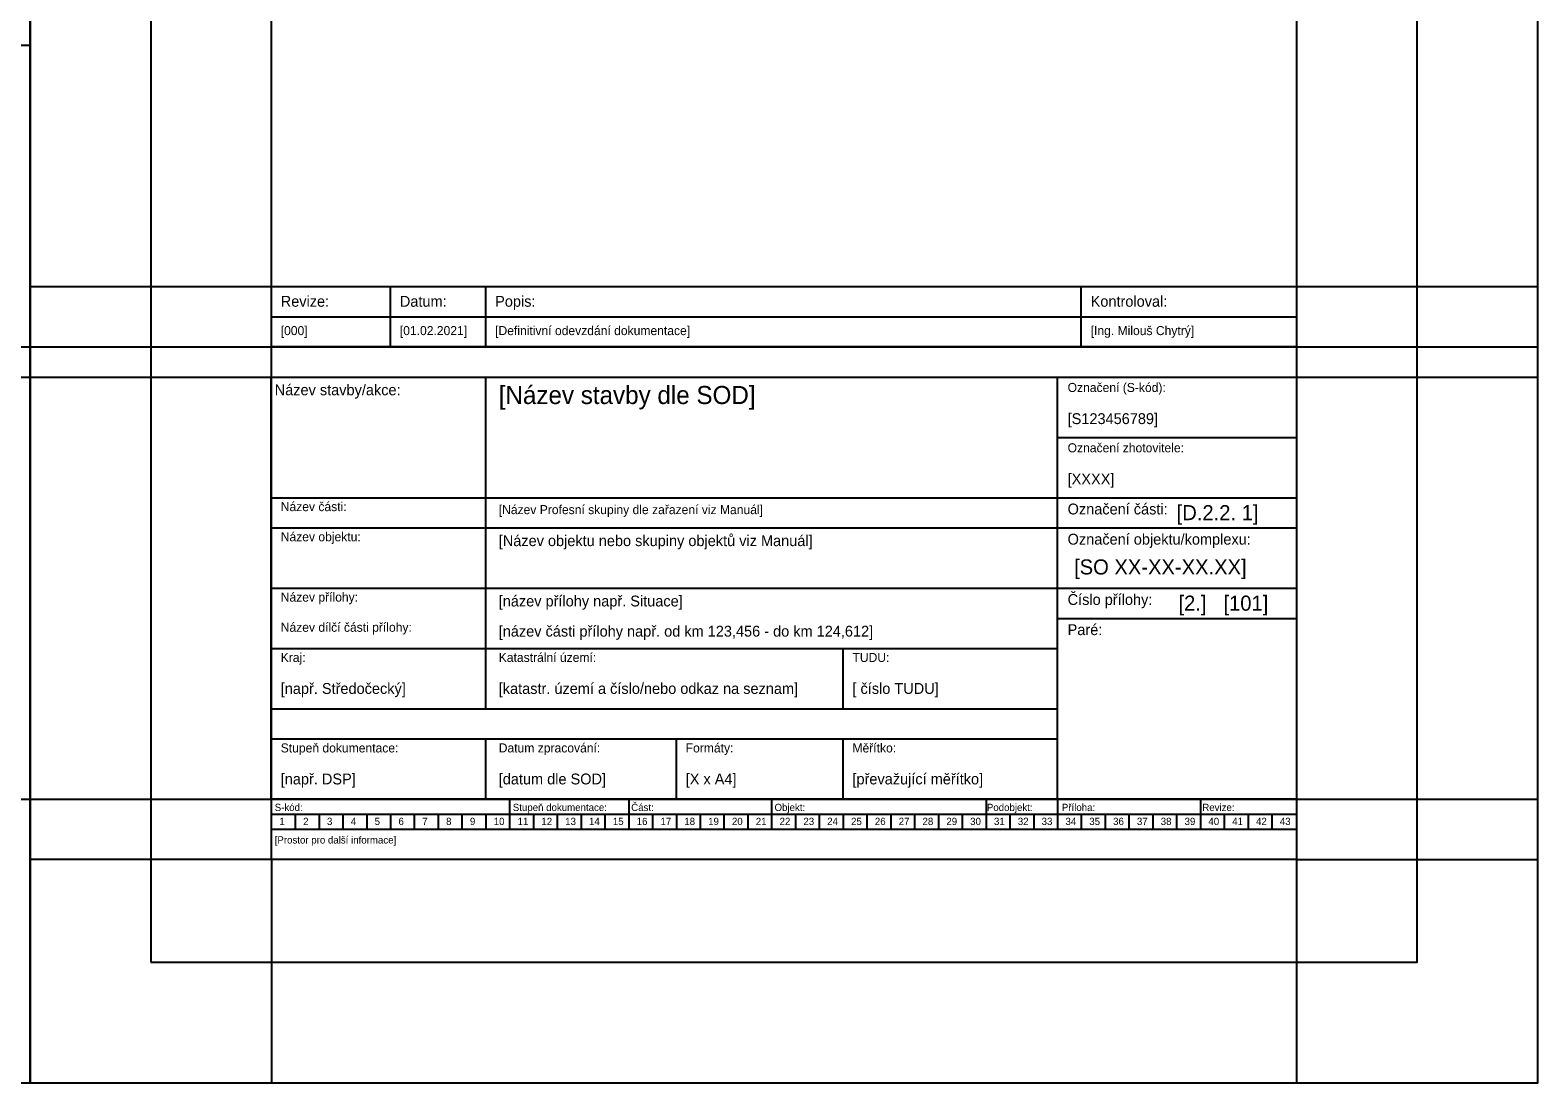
# Model space of a CAD drawing. Extents: x -27 to 48, y -2 to 33.
# Drawn here: x 23 to 48, y -2 to 15.45 of the extents above; entities that cross this region are included whole.
import ezdxf

# ---------------------------------------------------------------- set-up
doc = ezdxf.new("R2010")
doc.units = 0
for name, color, linetype in [('Default', 7, 'Continuous'), ('Rozpiska_pole_1', 7, 'Continuous'), ('Rozpiska_pole_4', 7, 'Continuous'), ('Rozpiska_pole_7', 7, 'Continuous'), ('Rozpiska_pole_8', 7, 'Continuous')]:
    doc.layers.add(name, color=color, linetype=linetype)

msp = doc.modelspace()

# ---------------------------------------------------------------- linework, layer by layer
at = {"layer": 'Default'}
for p, q in [((-2, 15.2), (23, 15.2)), ((23, 11.2), (48, 11.2)), ((-2, 10.2), (23, 10.2)), ((23, 10.2), (48, 10.2)), ((-2, 9.7), (23, 9.7)), ((23, 9.7), (48, 9.7)), ((-2, 2.7), (23, 2.7)), ((23, 2.7), (48, 2.7)), ((27, 1.7), (23, 1.7)), ((27, 1.7), (27, -2)), ((44, 1.7), (48, 1.7)), ((44, 1.7), (44, -2))]:
    msp.add_line(p, q, dxfattribs=at)
for points in [[(-2, -2), (23, -2), (23, 31.7), (-2, 31.7)], [(23, -2), (48, -2), (48, 31.7), (23, 31.7)], [(25, 0), (46, 0), (46, 29.7), (25, 29.7)]]:
    msp.add_lwpolyline(points, close=True, dxfattribs=at)
at = {"layer": 'Rozpiska_pole_1'}
msp.add_lwpolyline([(27, 27.7), (44, 27.7), (44, 1.7), (27, 1.7)], close=True, dxfattribs=at)
at = {"layer": 'Rozpiska_pole_4'}
for p, q in [((28.975, 10.2), (28.975, 11.2)), ((30.555, 10.2), (30.555, 11.2)), ((40.43, 10.2), (40.43, 11.2)), ((27, 10.7), (44, 10.7))]:
    msp.add_line(p, q, dxfattribs=at)
msp.add_lwpolyline([(27, 11.2), (44, 11.2), (44, 10.2), (27, 10.2)], close=True, dxfattribs=at)
at = {"layer": 'Rozpiska_pole_7'}
for p, q in [((30.555, 4.2), (30.555, 9.7)), ((40.035, 8.7), (44, 8.7)), ((27, 7.7), (40.035, 7.7)), ((40.035, 7.7), (44, 7.7)), ((27, 7.2), (40.035, 7.2)), ((40.035, 7.2), (44, 7.2)), ((27, 6.2), (40.035, 6.2)), ((40.035, 6.2), (44, 6.2)), ((40.035, 5.7), (44, 5.7)), ((27, 5.2), (40.035, 5.2)), ((36.48, 4.2), (36.48, 5.2)), ((27, 4.2), (40.035, 4.2)), ((27, 3.7), (40.035, 3.7)), ((30.555, 2.7), (30.555, 3.7)), ((33.715, 2.7), (33.715, 3.7)), ((36.48, 2.7), (36.48, 3.7))]:
    msp.add_line(p, q, dxfattribs=at)
for points in [[(26.999, 9.7), (43.999, 9.7), (43.999, 2.7), (26.999, 2.7)], [(44, 2.7), (40.035, 2.7), (40.035, 9.7), (44, 9.7)]]:
    msp.add_lwpolyline(points, close=True, dxfattribs=at)
at = {"layer": 'Rozpiska_pole_8'}
for p, q in [((30.95, 2.7), (30.95, 2.2)), ((32.925, 2.7), (32.925, 2.2)), ((35.295, 2.7), (35.295, 2.2)), ((38.85, 2.7), (38.85, 2.2)), ((40.035, 2.7), (40.035, 2.2)), ((42.405, 2.7), (42.405, 2.2)), ((44, 2.45), (27, 2.45)), ((27.395, 2.45), (27.395, 2.2)), ((27.79, 2.45), (27.79, 2.2)), ((28.185, 2.45), (28.185, 2.2)), ((28.58, 2.45), (28.58, 2.2)), ((28.975, 2.45), (28.975, 2.2)), ((29.37, 2.45), (29.37, 2.2)), ((29.765, 2.45), (29.765, 2.2)), ((30.16, 2.45), (30.16, 2.2)), ((30.555, 2.45), (30.555, 2.2)), ((31.345, 2.45), (31.345, 2.2)), ((31.74, 2.45), (31.74, 2.2)), ((32.135, 2.45), (32.135, 2.2)), ((32.53, 2.45), (32.53, 2.2)), ((33.32, 2.45), (33.32, 2.2)), ((33.715, 2.45), (33.715, 2.2)), ((34.11, 2.45), (34.11, 2.2)), ((34.505, 2.45), (34.505, 2.2)), ((34.9, 2.45), (34.9, 2.2)), ((35.69, 2.45), (35.69, 2.2)), ((36.085, 2.45), (36.085, 2.2)), ((36.48, 2.45), (36.48, 2.2)), ((36.875, 2.45), (36.875, 2.2)), ((37.27, 2.45), (37.27, 2.2)), ((37.665, 2.45), (37.665, 2.2)), ((38.06, 2.45), (38.06, 2.2)), ((38.455, 2.45), (38.455, 2.2)), ((39.245, 2.45), (39.245, 2.2)), ((39.64, 2.45), (39.64, 2.2)), ((40.43, 2.45), (40.43, 2.2)), ((40.825, 2.45), (40.825, 2.2)), ((41.22, 2.45), (41.22, 2.2)), ((41.615, 2.45), (41.615, 2.2)), ((42.01, 2.45), (42.01, 2.2)), ((42.8, 2.45), (42.8, 2.2)), ((43.195, 2.45), (43.195, 2.2)), ((43.59, 2.45), (43.59, 2.2))]:
    msp.add_line(p, q, dxfattribs=at)
msp.add_lwpolyline([(27, 2.7), (44, 2.7), (44, 2.2), (27, 2.2)], close=True, dxfattribs=at)

# ---------------------------------------------------------------- texts
at = {"layer": 'Rozpiska_pole_4'}
for s, height, p in [('Revize:', 0.18, (27.155, 10.865)), ('Datum:', 0.18, (29.13, 10.865)), ('Popis:', 0.18, (30.71, 10.865)), ('Kontroloval:', 0.18, (40.585, 10.865)), ('[000]', 0.15, (27.155, 10.395)), ('[01.02.2021]', 0.15, (29.13, 10.395)), ('[Definitivní odevzdání dokumentace]', 0.15, (30.71, 10.395)), ('[Ing. Milouš Chytrý]', 0.15, (40.585, 10.395))]:
    msp.add_text(s, height=height, dxfattribs=at).set_placement(p)
at = {"layer": 'Rozpiska_pole_7'}
for s, height, p in [('Název stavby/akce:', 0.18, (27.055, 9.397)), ('[Název stavby dle SOD]', 0.3, (30.77, 9.252)), ('Označení (S-kód):', 0.15, (40.203, 9.452)), ('[S123456789]', 0.18, (40.203, 8.92)), ('Označení zhotovitele:', 0.15, (40.203, 8.452)), ('[XXXX]', 0.18, (40.203, 7.92)), ('Název části:', 0.15, (27.155, 7.477)), ('[Název Profesní skupiny dle zařazení viz Manuál]', 0.15, (30.77, 7.427)), ('Označení části:', 0.18, (40.203, 7.422)), ('[D.2.2. 1]', 0.25, (42.011, 7.327)), ('Název objektu:', 0.15, (27.155, 6.977)), ('[Název objektu nebo skupiny objektů viz Manuál]', 0.18, (30.77, 6.897)), ('Označení objektu/komplexu:', 0.18, (40.203, 6.922)), ('[SO XX-XX-XX.XX]', 0.25, (40.31, 6.427)), ('Název přílohy:', 0.15, (27.155, 5.977)), ('[název přílohy např. Situace]', 0.18, (30.77, 5.897)), ('Číslo přílohy:', 0.18, (40.203, 5.922)), ('[2.]', 0.25, (42.041, 5.827)), ('[101]', 0.25, (42.787, 5.827)), ('Název dílčí části přílohy:', 0.15, (27.155, 5.477)), ('[název části přílohy např. od km 123,456 - do km 124,612]', 0.18, (30.77, 5.397)), ('Paré:', 0.18, (40.203, 5.422)), ('Kraj:', 0.15, (27.155, 4.977)), ('Katastrální území:', 0.15, (30.77, 4.977)), ('TUDU:', 0.15, (36.635, 4.977)), ('[např. Středočecký]', 0.18, (27.155, 4.447)), ('[katastr. území a číslo/nebo odkaz na seznam]', 0.18, (30.77, 4.447)), ('[ číslo TUDU]', 0.18, (36.635, 4.447)), ('Stupeň dokumentace:', 0.15, (27.155, 3.477)), ('Datum zpracování:', 0.15, (30.77, 3.477)), ('Formáty:', 0.15, (33.87, 3.477)), ('Měřítko:', 0.15, (36.635, 3.477)), ('[např. DSP]', 0.18, (27.155, 2.947)), ('[datum dle SOD]', 0.18, (30.77, 2.947)), ('[X x A4]', 0.18, (33.87, 2.947)), ('[převažující měřítko]', 0.18, (36.635, 2.947))]:
    msp.add_text(s, height=height, dxfattribs=at).set_placement(p)
at = {"layer": 'Rozpiska_pole_8'}
for s, p in [('S-kód:', (27.055, 2.506)), ('Stupeň dokumentace:', (31.003, 2.506)), ('Část:', (32.966, 2.506)), ('Objekt:', (35.343, 2.506)), ('Podobjekt:', (38.864, 2.506)), ('Příloha:', (40.107, 2.506)), ('Revize:', (42.436, 2.506)), ('1', (27.132, 2.274)), ('2', (27.527, 2.274)), ('3', (27.922, 2.274)), ('4', (28.317, 2.274)), ('5', (28.712, 2.274)), ('6', (29.107, 2.274)), ('7', (29.502, 2.274)), ('8', (29.897, 2.274)), ('9', (30.292, 2.274)), ('10', (30.687, 2.274)), ('11', (31.082, 2.274)), ('12', (31.477, 2.274)), ('13', (31.872, 2.274)), ('14', (32.267, 2.274)), ('15', (32.662, 2.274)), ('16', (33.057, 2.274)), ('17', (33.452, 2.274)), ('18', (33.847, 2.274)), ('19', (34.242, 2.274)), ('20', (34.637, 2.274)), ('21', (35.032, 2.274)), ('22', (35.427, 2.274)), ('23', (35.822, 2.274)), ('24', (36.217, 2.274)), ('25', (36.612, 2.274)), ('26', (37.007, 2.274)), ('27', (37.402, 2.274)), ('28', (37.797, 2.274)), ('29', (38.192, 2.274)), ('30', (38.587, 2.274)), ('31', (38.982, 2.274)), ('32', (39.377, 2.274)), ('33', (39.772, 2.274)), ('34', (40.167, 2.274)), ('35', (40.562, 2.274)), ('36', (40.957, 2.274)), ('37', (41.352, 2.274)), ('38', (41.747, 2.274)), ('39', (42.142, 2.274)), ('40', (42.537, 2.274)), ('41', (42.932, 2.274)), ('42', (43.327, 2.274)), ('43', (43.722, 2.274)), ('[Prostor pro další informace]', (27.055, 1.967))]:
    msp.add_text(s, height=0.12, dxfattribs=at).set_placement(p)

doc.saveas('drawing.dxf')
